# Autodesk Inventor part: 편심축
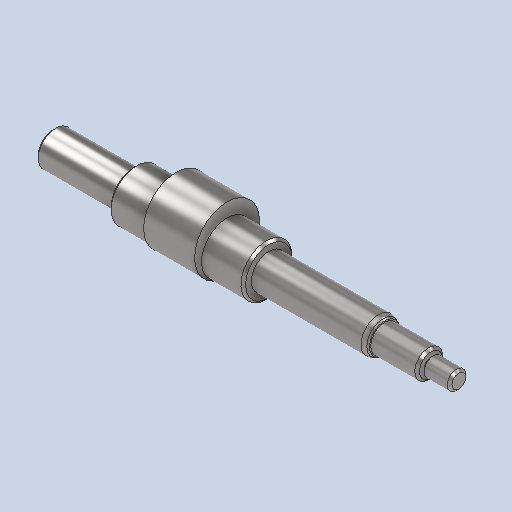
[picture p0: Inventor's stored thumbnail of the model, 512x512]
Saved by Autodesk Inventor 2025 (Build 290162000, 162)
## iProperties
Created: 2024-07
Part Number: 편심축
Material: 강철, 연강
Document SubType Name: Modeling
Designer: anfro
Density: 7.86 g/cm^3
Appearance: 기본값
Author: jhkim
Sending System: Autodesk Inventor 2025
Preprocessor: ST-DEVELOPER v20
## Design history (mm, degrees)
feature "솔리드1"
node "솔리드2"
